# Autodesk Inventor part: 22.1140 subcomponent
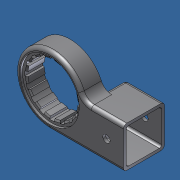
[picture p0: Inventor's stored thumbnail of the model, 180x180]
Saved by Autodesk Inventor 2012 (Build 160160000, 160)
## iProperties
Created: 2014-04
Part Number: 22.1140 subcomponent
Material: ABS Plastic
Document SubType Name: Modeling
Designer: Admin
Density: 1.06 g/cm^3
Mass: 42.8095 g
Surface Area: 196.539 cm^2
Volume: 40.3863 cm^3
Description: MULTI CONNECTOR 30 BODY SUBCOMPONENT
Stock Number: 22.1140 MULTI CONNECTOR 30 BODY SUBCOMPONENT
Translation Standard: STEP AP214IS
FileName: 22_1140_0_1.stp
PreProcessor: ACIS
PostProcessor: Build: 160, Release: 2012 RTM - Date: Tue 03/01/2011
Sent Units: inch
Uncertainty: 0.0
Author: Admin
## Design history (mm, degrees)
node "81"
node "Base1"
body "Solid1"
